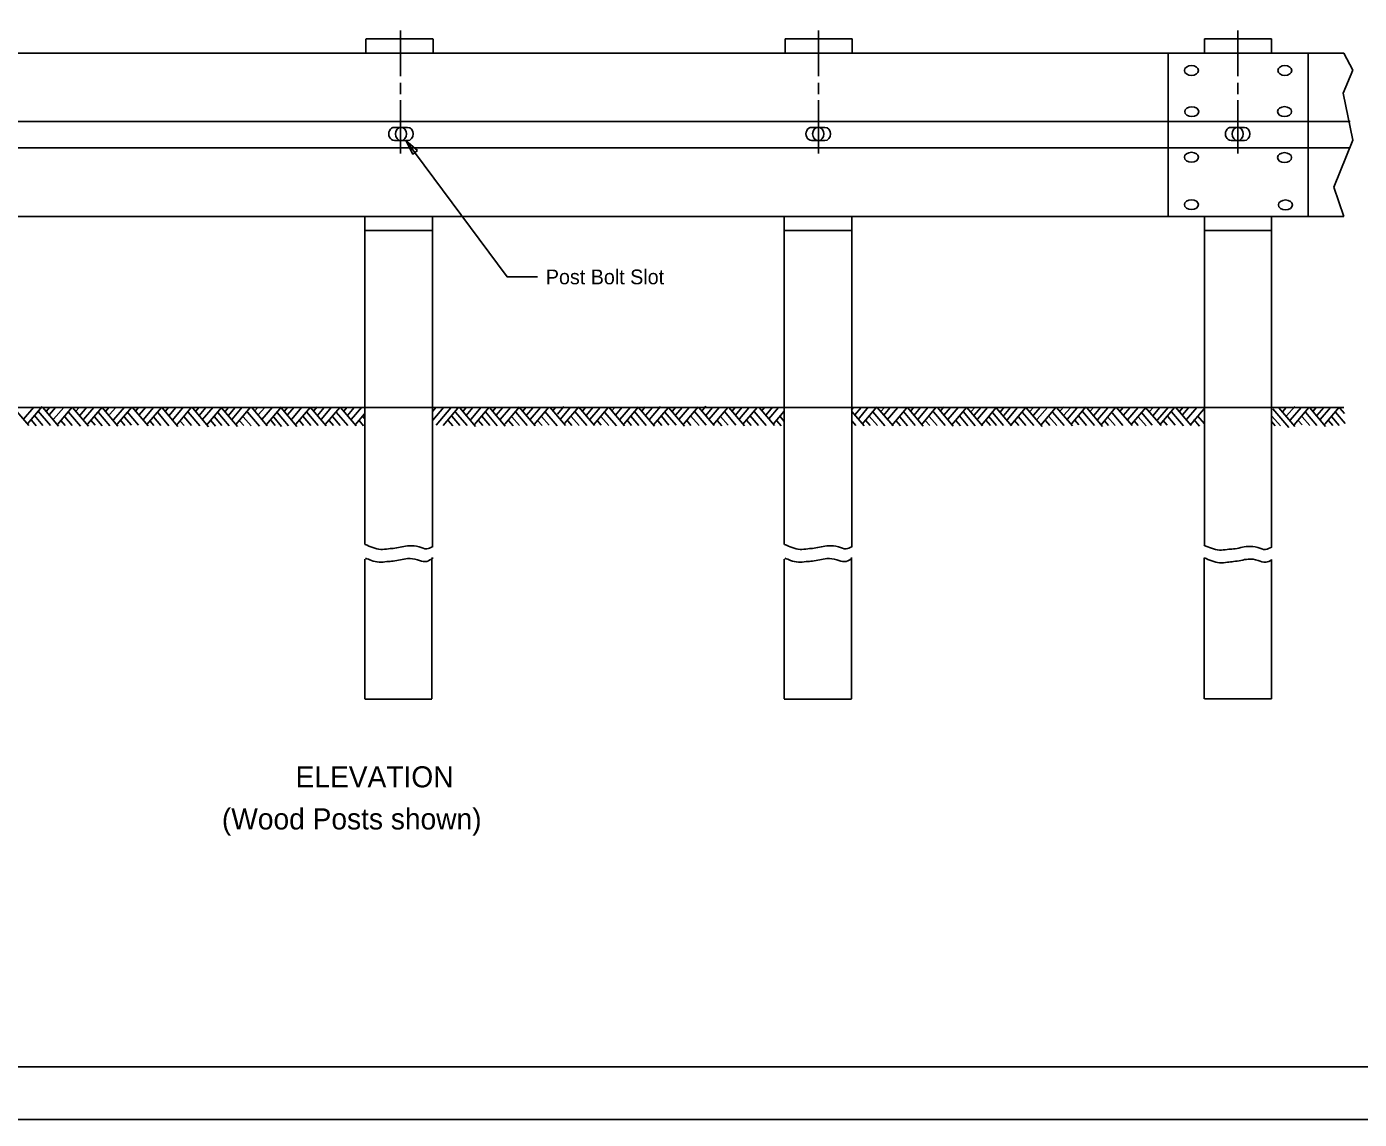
# Model space of a CAD drawing. Extents: x 0 to 34, y 0 to 22.
# Drawn here: x 9.94 to 22.61, y 0 to 10.38 of the extents above; entities that cross this region are included whole.
import ezdxf

# ---------------------------------------------------------------- set-up
doc = ezdxf.new("R2010")
doc.units = 0
for name, color, linetype in [('SH_Border', 7, 'Continuous'), ('SH_Cut_Line', 7, 'Continuous'), ('ST_Details', 7, 'Continuous'), ('ST_Text', 7, 'Continuous')]:
    doc.layers.add(name, color=color, linetype=linetype)

msp = doc.modelspace()

# ---------------------------------------------------------------- linework, layer by layer
at = {"layer": 'SH_Border'}
msp.add_lwpolyline([(2, 21.5), (33.5, 21.5), (33.5, 0.5), (2, 0.5)], close=True, dxfattribs=at)
at = {"layer": 'SH_Cut_Line'}
msp.add_lwpolyline([(0, 0), (34, 0), (34, 22), (0, 22)], close=True, dxfattribs=at)
at = {"layer": 'ST_Details'}
for p, q in [((13.167, 10.264), (13.805, 10.264)), ((13.167, 10.129), (13.167, 10.263)), ((13.497, 9.909), (13.497, 10.344)), ((13.805, 10.129), (13.805, 10.263)), ((17.151, 10.264), (17.789, 10.264)), ((17.151, 10.129), (17.151, 10.264)), ((17.469, 9.909), (17.469, 10.344)), ((17.789, 10.129), (17.789, 10.264)), ((21.136, 10.264), (21.773, 10.264)), ((21.136, 10.129), (21.136, 10.264)), ((21.453, 9.909), (21.453, 10.344)), ((21.773, 10.129), (21.773, 10.264)), ((3.972, 10.129), (22.458, 10.129)), ((20.789, 8.576), (20.789, 10.129)), ((22.121, 8.577), (22.121, 10.129)), ((22.458, 10.129), (22.546, 9.966)), ((22.546, 9.966), (22.454, 9.75)), ((13.497, 9.738), (13.497, 9.847)), ((17.469, 9.738), (17.469, 9.847)), ((21.453, 9.738), (21.453, 9.847)), ((13.497, 9.176), (13.497, 9.681)), ((17.469, 9.176), (17.469, 9.681)), ((21.453, 9.176), (21.453, 9.681)), ((22.454, 9.75), (22.546, 9.303)), ((4.185, 9.48), (22.518, 9.48)), ((13.438, 9.423), (13.501, 9.423)), ((13.501, 9.423), (13.564, 9.423)), ((17.402, 9.423), (17.465, 9.423)), ((17.465, 9.423), (17.528, 9.423)), ((21.387, 9.423), (21.45, 9.423)), ((21.45, 9.423), (21.514, 9.423)), ((13.501, 9.298), (13.438, 9.298)), ((13.564, 9.298), (13.501, 9.298)), ((17.465, 9.298), (17.402, 9.298)), ((17.528, 9.298), (17.465, 9.298)), ((21.45, 9.298), (21.387, 9.298)), ((21.514, 9.298), (21.45, 9.298)), ((22.546, 9.303), (22.363, 8.857)), ((4.153, 9.228), (22.515, 9.228)), ((22.363, 8.857), (22.458, 8.576)), ((3.972, 8.576), (22.458, 8.576)), ((13.158, 5.461), (13.158, 8.576)), ((13.799, 5.437), (13.799, 8.576)), ((17.142, 6.762), (17.142, 8.576)), ((17.142, 8.576), (17.142, 8.293)), ((17.783, 5.437), (17.783, 8.576)), ((17.783, 8.576), (17.783, 8.331)), ((21.136, 5.453), (21.136, 8.577)), ((21.773, 5.437), (21.773, 8.576)), ((13.158, 8.444), (13.799, 8.444)), ((17.142, 8.444), (17.783, 8.444)), ((21.136, 8.444), (21.773, 8.444)), ((3.972, 6.764), (22.458, 6.764)), ((9.965, 6.593), (9.814, 6.769)), ((9.816, 6.764), (13.158, 6.764)), ((9.914, 6.651), (10.011, 6.765)), ((9.952, 6.607), (10.092, 6.772)), ((10.17, 6.592), (10.054, 6.729)), ((10.248, 6.585), (10.097, 6.762)), ((10.129, 6.725), (10.163, 6.765)), ((10.16, 6.695), (10.218, 6.763)), ((10.2, 6.651), (10.296, 6.763)), ((10.238, 6.6), (10.378, 6.765)), ((10.456, 6.585), (10.343, 6.718)), ((10.531, 6.585), (10.38, 6.762)), ((10.415, 6.732), (10.439, 6.76)), ((10.446, 6.684), (10.515, 6.765)), ((10.484, 6.648), (10.582, 6.763)), ((10.521, 6.604), (10.66, 6.767)), ((10.733, 6.588), (10.626, 6.714)), ((10.811, 6.585), (10.66, 6.762)), ((10.695, 6.728), (10.725, 6.763)), ((10.732, 6.695), (10.79, 6.763)), ((10.77, 6.644), (10.873, 6.765)), ((10.804, 6.604), (10.943, 6.767)), ((11.007, 6.596), (10.9, 6.722)), ((11.097, 6.589), (10.947, 6.766)), ((10.981, 6.732), (11.008, 6.763)), ((11.012, 6.692), (11.075, 6.765)), ((11.05, 6.644), (11.149, 6.761)), ((11.087, 6.6), (11.224, 6.761)), ((11.296, 6.588), (11.189, 6.714)), ((11.38, 6.582), (11.23, 6.758)), ((11.261, 6.725), (11.296, 6.765)), ((11.298, 6.688), (11.359, 6.76)), ((11.326, 6.64), (11.425, 6.756)), ((11.367, 6.596), (11.51, 6.765)), ((11.589, 6.588), (11.479, 6.718)), ((11.672, 6.578), (11.522, 6.755)), ((11.55, 6.728), (11.58, 6.763)), ((11.582, 6.688), (11.646, 6.763)), ((11.613, 6.644), (11.717, 6.767)), ((11.653, 6.596), (11.797, 6.765)), ((11.867, 6.587), (11.759, 6.714)), ((11.946, 6.582), (11.796, 6.758)), ((11.83, 6.725), (11.863, 6.763)), ((11.858, 6.684), (11.926, 6.763)), ((11.896, 6.651), (11.992, 6.765)), ((11.93, 6.6), (12.072, 6.767)), ((12.155, 6.585), (12.042, 6.718)), ((12.229, 6.589), (12.079, 6.766)), ((12.11, 6.728), (12.14, 6.763)), ((12.145, 6.692), (12.206, 6.763)), ((12.179, 6.648), (12.279, 6.765)), ((12.222, 6.6), (12.366, 6.769)), ((12.433, 6.587), (12.325, 6.715)), ((12.512, 6.582), (12.362, 6.758)), ((12.39, 6.725), (12.425, 6.765)), ((12.421, 6.692), (12.486, 6.767)), ((12.462, 6.651), (12.557, 6.763)), ((12.502, 6.604), (12.641, 6.767)), ((12.713, 6.591), (12.603, 6.721)), ((12.79, 6.587), (12.64, 6.764)), ((12.67, 6.728), (12.704, 6.768)), ((12.707, 6.688), (12.771, 6.764)), ((12.741, 6.649), (12.84, 6.765)), ((12.78, 6.6), (12.919, 6.763)), ((12.996, 6.59), (12.886, 6.719)), ((13.075, 6.587), (12.925, 6.764)), ((12.958, 6.728), (12.989, 6.765)), ((12.993, 6.688), (13.057, 6.764)), ((13.027, 6.647), (13.128, 6.766)), ((13.799, 6.724), (13.834, 6.766)), ((13.799, 6.764), (17.142, 6.764)), ((13.803, 6.643), (13.909, 6.767)), ((13.835, 6.596), (13.974, 6.76)), ((13.902, 6.593), (14.041, 6.756)), ((14.128, 6.59), (14.016, 6.721)), ((14.21, 6.583), (14.06, 6.76)), ((14.091, 6.728), (14.124, 6.766)), ((14.12, 6.688), (14.183, 6.763)), ((14.163, 6.647), (14.264, 6.766)), ((14.198, 6.602), (14.337, 6.765)), ((14.416, 6.589), (14.304, 6.721)), ((14.491, 6.585), (14.341, 6.762)), ((14.374, 6.729), (14.402, 6.762)), ((14.404, 6.689), (14.464, 6.759)), ((14.443, 6.648), (14.54, 6.762)), ((14.488, 6.604), (14.627, 6.768)), ((14.7, 6.592), (14.592, 6.719)), ((14.775, 6.588), (14.625, 6.765)), ((14.657, 6.729), (14.687, 6.764)), ((14.692, 6.689), (14.753, 6.76)), ((14.727, 6.648), (14.825, 6.763)), ((14.766, 6.602), (14.905, 6.765)), ((14.985, 6.588), (14.867, 6.726)), ((15.065, 6.59), (14.915, 6.767)), ((14.943, 6.732), (14.97, 6.764)), ((14.987, 6.699), (15.048, 6.771)), ((15.015, 6.653), (15.107, 6.761)), ((15.054, 6.61), (15.189, 6.769)), ((15.266, 6.592), (15.153, 6.724)), ((15.34, 6.59), (15.19, 6.767)), ((15.227, 6.732), (15.254, 6.763)), ((15.262, 6.691), (15.323, 6.763)), ((15.295, 6.648), (15.392, 6.762)), ((15.333, 6.602), (15.472, 6.765)), ((15.548, 6.587), (15.435, 6.719)), ((15.624, 6.588), (15.474, 6.765)), ((15.505, 6.732), (15.531, 6.763)), ((15.539, 6.691), (15.602, 6.765)), ((15.58, 6.648), (15.681, 6.766)), ((15.617, 6.605), (15.756, 6.768)), ((15.83, 6.593), (15.721, 6.721)), ((15.908, 6.585), (15.758, 6.762)), ((15.788, 6.729), (15.822, 6.769)), ((15.825, 6.686), (15.892, 6.764)), ((15.86, 6.645), (15.968, 6.772)), ((15.899, 6.597), (16.038, 6.76)), ((16.115, 6.594), (16.009, 6.719)), ((16.194, 6.585), (16.044, 6.762)), ((16.081, 6.729), (16.11, 6.763)), ((16.109, 6.691), (16.171, 6.764)), ((16.142, 6.648), (16.242, 6.766)), ((16.185, 6.604), (16.324, 6.768)), ((16.399, 6.596), (16.289, 6.726)), ((16.476, 6.59), (16.326, 6.767)), ((16.357, 6.726), (16.398, 6.775)), ((16.397, 6.688), (16.458, 6.76)), ((16.427, 6.65), (16.526, 6.765)), ((16.468, 6.599), (16.606, 6.763)), ((16.683, 6.596), (16.577, 6.72)), ((16.765, 6.587), (16.615, 6.764)), ((16.646, 6.729), (16.676, 6.764)), ((16.678, 6.691), (16.738, 6.761)), ((16.718, 6.655), (16.807, 6.76)), ((16.749, 6.605), (16.884, 6.764)), ((16.971, 6.591), (16.856, 6.726)), ((17.049, 6.593), (16.903, 6.764)), ((16.927, 6.729), (16.958, 6.766)), ((16.97, 6.694), (17.03, 6.765)), ((16.995, 6.655), (17.087, 6.764)), ((17.04, 6.608), (17.141, 6.727)), ((17.142, 5.461), (17.142, 6.762)), ((17.782, 6.74), (17.801, 6.762)), ((17.783, 6.764), (21.136, 6.764)), ((17.9, 6.587), (17.784, 6.723)), ((17.813, 6.694), (17.872, 6.764)), ((17.843, 6.65), (17.941, 6.765)), ((17.883, 6.605), (18.022, 6.768)), ((18.098, 6.587), (17.985, 6.72)), ((18.176, 6.587), (18.026, 6.764)), ((18.059, 6.723), (18.094, 6.764)), ((18.084, 6.688), (18.148, 6.764)), ((18.119, 6.644), (18.22, 6.762)), ((18.164, 6.593), (18.303, 6.757)), ((18.387, 6.59), (18.274, 6.723)), ((18.462, 6.584), (18.312, 6.761)), ((18.343, 6.726), (18.375, 6.765)), ((18.373, 6.688), (18.437, 6.763)), ((18.41, 6.65), (18.51, 6.767)), ((18.446, 6.599), (18.584, 6.763)), ((18.67, 6.59), (18.56, 6.72)), ((18.748, 6.584), (18.598, 6.761)), ((18.624, 6.726), (18.659, 6.768)), ((18.659, 6.691), (18.721, 6.764)), ((18.697, 6.647), (18.797, 6.765)), ((18.734, 6.599), (18.873, 6.763)), ((18.955, 6.588), (18.841, 6.723)), ((19.027, 6.587), (18.876, 6.764)), ((18.919, 6.723), (18.952, 6.762)), ((18.948, 6.689), (19.01, 6.761)), ((18.977, 6.651), (19.072, 6.763)), ((19.018, 6.599), (19.157, 6.763)), ((19.226, 6.591), (19.121, 6.715)), ((19.303, 6.587), (19.159, 6.757)), ((19.193, 6.719), (19.232, 6.765)), ((19.228, 6.685), (19.292, 6.761)), ((19.26, 6.644), (19.359, 6.761)), ((19.295, 6.596), (19.434, 6.759)), ((19.513, 6.59), (19.404, 6.719)), ((19.592, 6.583), (19.442, 6.76)), ((19.476, 6.723), (19.511, 6.764)), ((19.508, 6.685), (19.576, 6.766)), ((19.546, 6.651), (19.642, 6.764)), ((19.581, 6.596), (19.72, 6.759)), ((19.802, 6.59), (19.692, 6.719)), ((19.881, 6.587), (19.73, 6.763)), ((19.768, 6.733), (19.798, 6.769)), ((19.8, 6.689), (19.861, 6.76)), ((19.829, 6.647), (19.922, 6.757)), ((19.87, 6.606), (20.008, 6.769)), ((20.091, 6.59), (19.975, 6.726)), ((20.166, 6.583), (20.016, 6.76)), ((20.051, 6.73), (20.079, 6.764)), ((20.083, 6.685), (20.148, 6.762)), ((20.118, 6.644), (20.216, 6.76)), ((20.153, 6.599), (20.291, 6.763)), ((20.359, 6.593), (20.258, 6.712)), ((20.447, 6.59), (20.296, 6.767)), ((20.331, 6.726), (20.362, 6.764)), ((20.363, 6.685), (20.429, 6.764)), ((20.404, 6.644), (20.504, 6.762)), ((20.442, 6.603), (20.58, 6.766)), ((20.638, 6.595), (20.536, 6.715)), ((20.724, 6.59), (20.573, 6.767)), ((20.614, 6.723), (20.648, 6.764)), ((20.643, 6.682), (20.711, 6.762)), ((20.689, 6.644), (20.793, 6.765)), ((20.71, 6.599), (20.849, 6.763)), ((20.935, 6.588), (20.821, 6.722)), ((21.01, 6.59), (20.859, 6.767)), ((20.897, 6.723), (20.934, 6.767)), ((20.926, 6.692), (20.984, 6.76)), ((20.964, 6.647), (21.061, 6.762)), ((21.002, 6.599), (21.14, 6.763)), ((21.773, 6.764), (22.458, 6.764)), ((21.935, 6.573), (21.784, 6.75)), ((21.993, 6.583), (21.843, 6.76)), ((21.88, 6.726), (21.912, 6.764)), ((21.915, 6.682), (21.992, 6.772)), ((21.95, 6.641), (22.055, 6.764)), ((21.988, 6.599), (22.127, 6.763)), ((22.203, 6.59), (22.094, 6.719)), ((22.285, 6.583), (22.135, 6.76)), ((22.166, 6.726), (22.2, 6.767)), ((22.201, 6.685), (22.268, 6.764)), ((22.233, 6.647), (22.332, 6.764)), ((22.277, 6.603), (22.415, 6.766)), ((22.473, 6.609), (22.38, 6.719)), ((22.464, 6.705), (22.42, 6.757)), ((10.033, 6.588), (9.989, 6.641)), ((10.099, 6.592), (10.02, 6.685)), ((10.309, 6.59), (10.268, 6.638)), ((10.377, 6.59), (10.306, 6.674)), ((10.595, 6.594), (10.555, 6.641)), ((10.662, 6.588), (10.589, 6.674)), ((10.878, 6.59), (10.835, 6.641)), ((10.94, 6.594), (10.872, 6.674)), ((11.153, 6.592), (11.118, 6.634)), ((11.22, 6.59), (11.149, 6.674)), ((11.44, 6.592), (11.404, 6.634)), ((11.511, 6.592), (11.438, 6.678)), ((11.738, 6.585), (11.693, 6.638)), ((11.8, 6.592), (11.727, 6.678)), ((12.007, 6.59), (11.97, 6.634)), ((12.076, 6.587), (12.001, 6.674)), ((12.304, 6.592), (12.266, 6.638)), ((12.365, 6.583), (12.291, 6.671)), ((12.576, 6.593), (12.536, 6.64)), ((12.644, 6.59), (12.568, 6.679)), ((12.859, 6.591), (12.818, 6.64)), ((12.924, 6.591), (12.851, 6.677)), ((13.07, 6.6), (13.155, 6.701)), ((13.145, 6.589), (13.104, 6.638)), ((13.157, 6.656), (13.139, 6.677)), ((13.993, 6.589), (13.949, 6.64)), ((14.061, 6.59), (13.983, 6.681)), ((14.278, 6.591), (14.235, 6.642)), ((14.345, 6.59), (14.269, 6.679)), ((14.566, 6.589), (14.523, 6.64)), ((14.626, 6.593), (14.555, 6.675)), ((14.841, 6.59), (14.798, 6.64)), ((14.908, 6.595), (14.837, 6.678)), ((15.125, 6.591), (15.086, 6.637)), ((15.193, 6.59), (15.119, 6.678)), ((15.403, 6.596), (15.368, 6.637)), ((15.476, 6.59), (15.4, 6.678)), ((15.692, 6.592), (15.65, 6.642)), ((15.759, 6.593), (15.684, 6.681)), ((15.978, 6.592), (15.94, 6.637)), ((16.047, 6.595), (15.975, 6.68)), ((16.256, 6.592), (16.216, 6.64)), ((16.333, 6.591), (16.253, 6.684)), ((16.548, 6.588), (16.504, 6.64)), ((16.609, 6.594), (16.537, 6.678)), ((16.829, 6.592), (16.785, 6.643)), ((16.897, 6.592), (16.816, 6.687)), ((17.114, 6.587), (17.072, 6.637)), ((17.142, 6.631), (17.102, 6.678)), ((17.822, 6.59), (17.783, 6.636)), ((17.96, 6.59), (17.915, 6.643)), ((18.028, 6.59), (17.95, 6.681)), ((18.247, 6.589), (18.204, 6.64)), ((18.313, 6.589), (18.239, 6.675)), ((18.524, 6.591), (18.485, 6.637)), ((18.594, 6.591), (18.52, 6.678)), ((18.817, 6.589), (18.773, 6.64)), ((18.887, 6.589), (18.806, 6.684)), ((19.101, 6.591), (19.056, 6.643)), ((19.16, 6.59), (19.083, 6.681)), ((19.371, 6.593), (19.328, 6.643)), ((19.439, 6.591), (19.366, 6.678)), ((19.665, 6.593), (19.625, 6.64)), ((19.732, 6.59), (19.657, 6.678)), ((19.942, 6.597), (19.902, 6.643)), ((20.015, 6.593), (19.937, 6.684)), ((20.224, 6.592), (20.185, 6.636)), ((20.285, 6.592), (20.215, 6.674)), ((20.505, 6.593), (20.468, 6.636)), ((20.58, 6.588), (20.506, 6.674)), ((20.781, 6.595), (20.74, 6.643)), ((20.857, 6.595), (20.786, 6.678)), ((21.087, 6.585), (21.035, 6.647)), ((21.135, 6.607), (21.07, 6.684)), ((21.856, 6.587), (21.776, 6.681)), ((21.808, 6.588), (21.776, 6.626)), ((22.062, 6.599), (22.026, 6.64)), ((22.136, 6.59), (22.064, 6.674)), ((22.353, 6.592), (22.312, 6.64)), ((22.416, 6.59), (22.342, 6.678)), ((13.158, 3.994), (13.158, 5.322)), ((13.79, 5.331), (13.805, 5.331)), ((13.795, 3.994), (13.795, 5.327)), ((17.142, 3.994), (17.142, 5.322)), ((17.775, 5.331), (17.789, 5.331)), ((17.78, 3.994), (17.78, 5.327)), ((21.133, 3.994), (21.133, 5.333)), ((21.773, 3.994), (21.773, 5.319)), ((13.158, 3.993), (13.795, 3.993)), ((17.142, 3.993), (17.78, 3.993)), ((21.136, 3.996), (21.773, 3.996))]:
    msp.add_line(p, q, dxfattribs=at)
for centre, major_axis, ratio in [((21.011, 9.964), (-0.0664, 0), 0.705181), ((21.899, 9.964), (-0.0664, 0), 0.705181), ((21.014, 9.573), (-0.0664, 0), 0.705181), ((21.896, 9.574), (-0.0664, 0), 0.705181), ((13.501, 9.361), (0, 0.0625), 0.850089), ((17.465, 9.361), (0, 0.0625), 0.850089), ((21.45, 9.361), (0, 0.0625), 0.850089), ((21.011, 9.14), (-0.0664, 0), 0.705181), ((21.896, 9.137), (-0.0664, 0), 0.705181), ((21.011, 8.69), (-0.0664, 0), 0.705181), ((21.904, 8.687), (-0.0664, 0), 0.705181)]:
    msp.add_ellipse(centre, major_axis=major_axis, ratio=ratio, dxfattribs=at)
for centre, start_param, end_param in [((13.438, 9.361), 0, 3.141593), ((13.564, 9.361), 3.141593, 6.283185), ((17.402, 9.361), 0, 3.141593), ((17.528, 9.361), 3.141593, 6.283185), ((21.387, 9.361), 0, 3.141593), ((21.514, 9.361), 3.141593, 6.283185)]:
    msp.add_ellipse(centre, major_axis=(0, 0.0625), ratio=0.850089, start_param=start_param, end_param=end_param, dxfattribs=at)
for points in [[(13.16, 5.461), (13.234, 5.432), (13.308, 5.414), (13.382, 5.42), (13.441, 5.426), (13.51, 5.438), (13.579, 5.449), (13.673, 5.438), (13.747, 5.42), (13.798, 5.44)], [(17.145, 5.461), (17.218, 5.432), (17.292, 5.414), (17.366, 5.42), (17.425, 5.426), (17.494, 5.438), (17.563, 5.449), (17.657, 5.438), (17.731, 5.42), (17.782, 5.44)], [(21.129, 5.454), (21.203, 5.425), (21.277, 5.408), (21.35, 5.414), (21.41, 5.419), (21.479, 5.431), (21.548, 5.443), (21.641, 5.431), (21.715, 5.414), (21.774, 5.437)], [(13.164, 5.331), (13.219, 5.31), (13.293, 5.293), (13.367, 5.298), (13.426, 5.304), (13.495, 5.316), (13.564, 5.327), (13.657, 5.316), (13.731, 5.298), (13.79, 5.322)], [(17.148, 5.331), (17.203, 5.31), (17.277, 5.293), (17.351, 5.298), (17.41, 5.304), (17.479, 5.316), (17.548, 5.327), (17.641, 5.316), (17.715, 5.298), (17.775, 5.322)], [(21.132, 5.334), (21.205, 5.305), (21.279, 5.287), (21.353, 5.293), (21.412, 5.299), (21.481, 5.31), (21.55, 5.322), (21.644, 5.31), (21.718, 5.293), (21.772, 5.314)]]:
    msp.add_spline(points, degree=3, dxfattribs=at)
at = {"layer": 'ST_Text'}
msp.add_lwpolyline([(13.548, 9.298), (14.508, 8.005), (14.799, 8.005)], dxfattribs=at)
msp.add_lwpolyline([(13.657, 9.205), (13.548, 9.298), (13.612, 9.17)], close=True, dxfattribs=at)

# ---------------------------------------------------------------- texts
msp.add_text('Post Bolt Slot', height=0.14, rotation=360, dxfattribs=at).set_placement((14.877, 7.933))
for s, p in [('ELEVATION', (12.499, 3.154)), ('(Wood Posts shown)', (11.799, 2.754))]:
    msp.add_text(s, height=0.2, dxfattribs=at).set_placement(p)

doc.saveas('drawing.dxf')
